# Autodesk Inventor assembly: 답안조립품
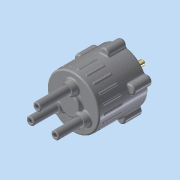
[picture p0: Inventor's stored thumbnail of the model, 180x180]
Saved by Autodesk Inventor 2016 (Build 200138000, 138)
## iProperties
Created: 2015-11
Part Number: 답안조립품
Material: 일반
Document SubType Name: Assembly
Designer: Administrator
Author: Administrator
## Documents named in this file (14)
- C:\Users\Administrator\Desktop\inventor 1급-김병하\1급\답안조립품.iam
- C:\Users\Administrator\Desktop\inventor 1급-김병하\1급\본체.ipt
- C:\Users\Administrator\Desktop\inventor 1급-김병하\1급\커버.ipt
- C:\Users\Administrator\Desktop\inventor 1급-김병하\1급\베어링 NA 4900.ipt
- C:\Users\Administrator\Desktop\inventor 1급-김병하\1급\메인 축.ipt
- C:\Users\Administrator\Desktop\inventor 1급-김병하\1급\멈춤링 22 x 1.2.ipt
- C:\Users\Administrator\Desktop\inventor 1급-김병하\1급\판캠.ipt
- C:\Users\Administrator\Desktop\inventor 1급-김병하\1급\슬라이드 축.ipt
- C:\Users\Administrator\Desktop\inventor 1급-김병하\1급\가변스프링-11.ipt
- C:\Users\Administrator\Desktop\inventor 1급-김병하\1급\가변스프링-12.ipt
- C:\Users\Administrator\Desktop\inventor 1급-김병하\1급\가변스프링-13.ipt
- C:\Users\Administrator\Desktop\inventor 1급-김병하\1급\멈춤링 10 x 1.ipt
- C:\Users\Administrator\Desktop\inventor 1급-김병하\1급\오일실.ipt
- C:\Users\Administrator\Desktop\inventor 1급-김병하\1급\M5x0.8x20.ipt
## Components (8 placed, 4 different names)
1. 가변스프링-11:1
2. 가변스프링-12:1
3. 가변스프링-13:1
4. M5x0.8x20:1
5. M5x0.8x20:2
6. M5x0.8x20:3
7. M5x0.8x20:4
8. M5x0.8x20:5
